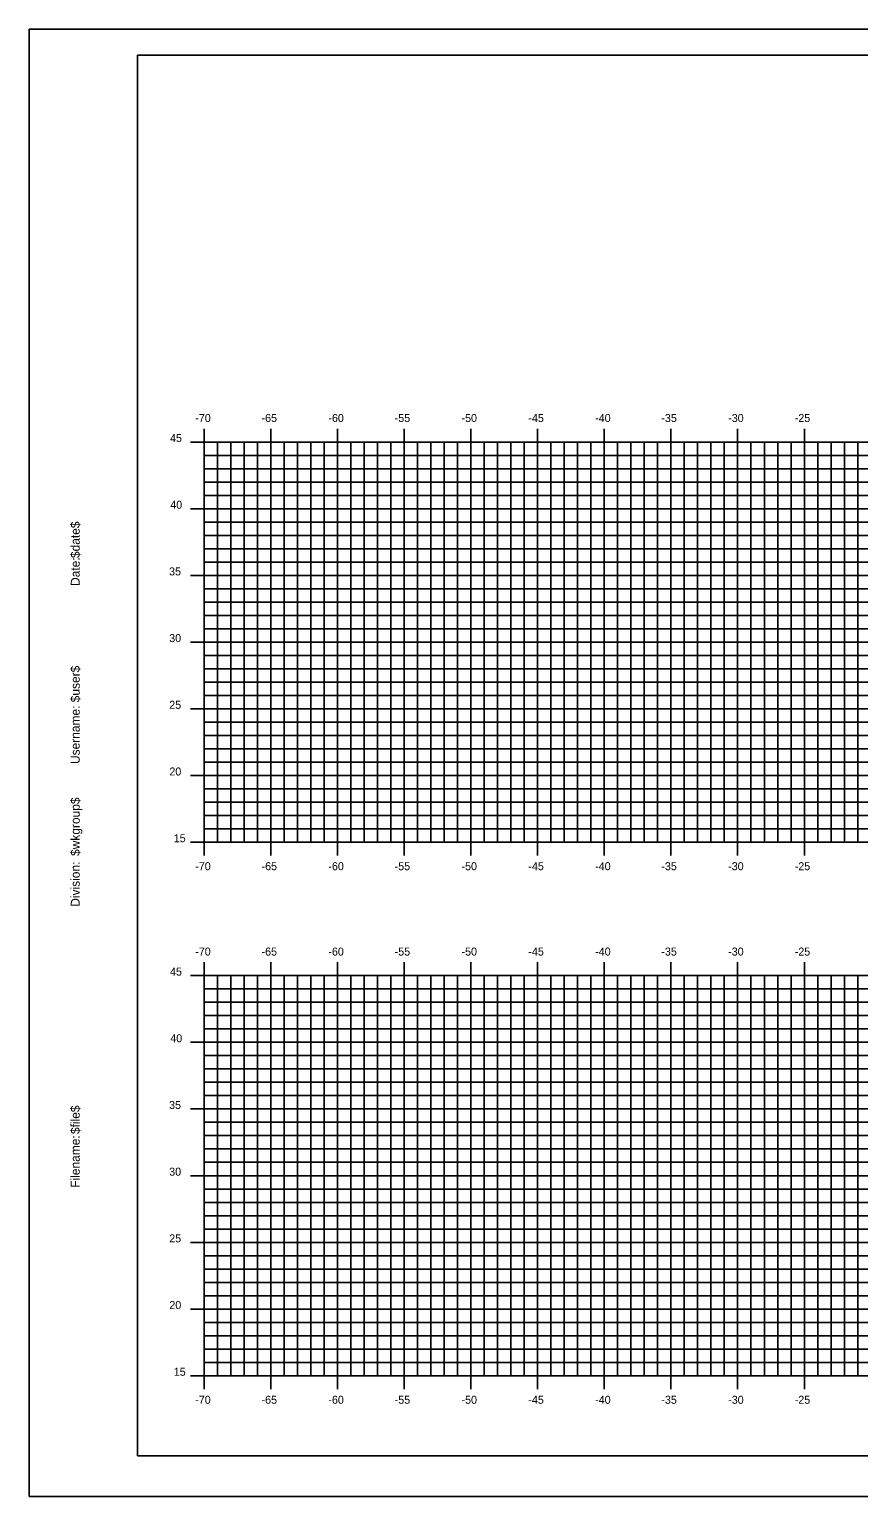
# Model space of a CAD drawing. Extents: x 1037709 to 1037879, y 394883 to 394993.
# Drawn here: x 1037709.1 to 1037771.2, y 394882.6 to 394992.6 of the extents above; entities that cross this region are included whole.
import ezdxf

# ---------------------------------------------------------------- set-up
doc = ezdxf.new("R2010")
doc.units = 0
for name, color, linetype in [('BORDER', 7, 'Continuous'), ('H_V ANNOTATION', 7, 'Continuous'), ('MAJOR', 7, 'Continuous'), ('MINOR', 7, 'Continuous'), ('PLOT BOUNDARY', 7, 'Continuous')]:
    doc.layers.add(name, color=color, linetype=linetype)

msp = doc.modelspace()

# ---------------------------------------------------------------- linework, layer by layer
at = {"layer": 'BORDER'}
for p, q in [((1037877.16, 394990.69), (1037717.16, 394990.69)), ((1037717.16, 394990.69), (1037717.16, 394885.69)), ((1037717.16, 394885.69), (1037877.16, 394885.69))]:
    msp.add_line(p, q, dxfattribs=at)
at = {"layer": 'MAJOR'}
for p, q in [((1037721.15, 394961.69), (1037722.16, 394961.69)), ((1037722.16, 394962.69), (1037722.16, 394961.69)), ((1037722.16, 394961.69), (1037862.16, 394961.69)), ((1037722.16, 394931.69), (1037722.16, 394961.69)), ((1037727.16, 394962.69), (1037727.16, 394961.69)), ((1037727.16, 394931.69), (1037727.16, 394961.69)), ((1037732.16, 394962.69), (1037732.16, 394961.69)), ((1037732.16, 394931.69), (1037732.16, 394961.69)), ((1037737.16, 394962.69), (1037737.16, 394961.69)), ((1037737.16, 394931.69), (1037737.16, 394961.69)), ((1037742.16, 394962.69), (1037742.16, 394961.69)), ((1037742.16, 394931.69), (1037742.16, 394961.69)), ((1037747.16, 394962.69), (1037747.16, 394961.69)), ((1037747.16, 394931.69), (1037747.16, 394961.69)), ((1037752.16, 394962.69), (1037752.16, 394961.69)), ((1037752.16, 394931.69), (1037752.16, 394961.69)), ((1037757.16, 394962.69), (1037757.16, 394961.69)), ((1037757.16, 394931.69), (1037757.16, 394961.69)), ((1037762.16, 394962.69), (1037762.16, 394961.69)), ((1037762.16, 394931.69), (1037762.16, 394961.69)), ((1037767.16, 394962.69), (1037767.16, 394961.69)), ((1037767.16, 394931.69), (1037767.16, 394961.69)), ((1037721.15, 394956.69), (1037722.16, 394956.69)), ((1037722.16, 394956.69), (1037862.16, 394956.69)), ((1037721.15, 394951.69), (1037722.16, 394951.69)), ((1037722.16, 394951.69), (1037862.16, 394951.69)), ((1037721.15, 394946.69), (1037722.16, 394946.69)), ((1037722.16, 394946.69), (1037862.16, 394946.69)), ((1037721.15, 394941.69), (1037722.16, 394941.69)), ((1037722.16, 394941.69), (1037862.16, 394941.69)), ((1037721.15, 394936.69), (1037722.16, 394936.69)), ((1037722.16, 394936.69), (1037862.16, 394936.69)), ((1037721.15, 394931.69), (1037722.16, 394931.69)), ((1037722.16, 394931.69), (1037862.16, 394931.69)), ((1037722.16, 394930.68), (1037722.16, 394931.69)), ((1037727.16, 394930.68), (1037727.16, 394931.69)), ((1037732.16, 394930.68), (1037732.16, 394931.69)), ((1037737.16, 394930.68), (1037737.16, 394931.69)), ((1037742.16, 394930.68), (1037742.16, 394931.69)), ((1037747.16, 394930.68), (1037747.16, 394931.69)), ((1037752.16, 394930.68), (1037752.16, 394931.69)), ((1037757.16, 394930.68), (1037757.16, 394931.69)), ((1037762.16, 394930.68), (1037762.16, 394931.69)), ((1037767.16, 394930.68), (1037767.16, 394931.69)), ((1037722.16, 394922.69), (1037722.16, 394921.69)), ((1037727.16, 394922.69), (1037727.16, 394921.69)), ((1037732.16, 394922.69), (1037732.16, 394921.69)), ((1037737.16, 394922.69), (1037737.16, 394921.69)), ((1037742.16, 394922.69), (1037742.16, 394921.69)), ((1037747.16, 394922.69), (1037747.16, 394921.69)), ((1037752.16, 394922.69), (1037752.16, 394921.69)), ((1037757.16, 394922.69), (1037757.16, 394921.69)), ((1037762.16, 394922.69), (1037762.16, 394921.69)), ((1037767.16, 394922.69), (1037767.16, 394921.69)), ((1037721.15, 394921.69), (1037722.16, 394921.69)), ((1037722.16, 394921.69), (1037862.16, 394921.69)), ((1037722.16, 394891.69), (1037722.16, 394921.69)), ((1037727.16, 394891.69), (1037727.16, 394921.69)), ((1037732.16, 394891.69), (1037732.16, 394921.69)), ((1037737.16, 394891.69), (1037737.16, 394921.69)), ((1037742.16, 394891.69), (1037742.16, 394921.69)), ((1037747.16, 394891.69), (1037747.16, 394921.69)), ((1037752.16, 394891.69), (1037752.16, 394921.69)), ((1037757.16, 394891.69), (1037757.16, 394921.69)), ((1037762.16, 394891.69), (1037762.16, 394921.69)), ((1037767.16, 394891.69), (1037767.16, 394921.69)), ((1037721.15, 394916.69), (1037722.16, 394916.69)), ((1037722.16, 394916.69), (1037862.16, 394916.69)), ((1037721.15, 394911.69), (1037722.16, 394911.69)), ((1037722.16, 394911.69), (1037862.16, 394911.69)), ((1037721.15, 394906.69), (1037722.16, 394906.69)), ((1037722.16, 394906.69), (1037862.16, 394906.69)), ((1037721.15, 394901.69), (1037722.16, 394901.69)), ((1037722.16, 394901.69), (1037862.16, 394901.69)), ((1037721.15, 394896.69), (1037722.16, 394896.69)), ((1037722.16, 394896.69), (1037862.16, 394896.69)), ((1037721.15, 394891.69), (1037722.16, 394891.69)), ((1037722.16, 394891.69), (1037862.16, 394891.69)), ((1037722.16, 394890.68), (1037722.16, 394891.69)), ((1037727.16, 394890.68), (1037727.16, 394891.69)), ((1037732.16, 394890.68), (1037732.16, 394891.69)), ((1037737.16, 394890.68), (1037737.16, 394891.69)), ((1037742.16, 394890.68), (1037742.16, 394891.69)), ((1037747.16, 394890.68), (1037747.16, 394891.69)), ((1037752.16, 394890.68), (1037752.16, 394891.69)), ((1037757.16, 394890.68), (1037757.16, 394891.69)), ((1037762.16, 394890.68), (1037762.16, 394891.69)), ((1037767.16, 394890.68), (1037767.16, 394891.69))]:
    msp.add_line(p, q, dxfattribs=at)
at = {"layer": 'MINOR'}
for p, q in [((1037723.16, 394931.69), (1037723.16, 394961.69)), ((1037724.16, 394931.69), (1037724.16, 394961.69)), ((1037725.16, 394931.69), (1037725.16, 394961.69)), ((1037726.16, 394931.69), (1037726.16, 394961.69)), ((1037728.16, 394931.69), (1037728.16, 394961.69)), ((1037729.16, 394931.69), (1037729.16, 394961.69)), ((1037730.16, 394931.69), (1037730.16, 394961.69)), ((1037731.16, 394931.69), (1037731.16, 394961.69)), ((1037733.16, 394931.69), (1037733.16, 394961.69)), ((1037734.16, 394931.69), (1037734.16, 394961.69)), ((1037735.16, 394931.69), (1037735.16, 394961.69)), ((1037736.16, 394931.69), (1037736.16, 394961.69)), ((1037738.16, 394931.69), (1037738.16, 394961.69)), ((1037739.16, 394931.69), (1037739.16, 394961.69)), ((1037740.16, 394931.69), (1037740.16, 394961.69)), ((1037741.16, 394931.69), (1037741.16, 394961.69)), ((1037743.16, 394931.69), (1037743.16, 394961.69)), ((1037744.16, 394931.69), (1037744.16, 394961.69)), ((1037745.16, 394931.69), (1037745.16, 394961.69)), ((1037746.16, 394931.69), (1037746.16, 394961.69)), ((1037748.16, 394931.69), (1037748.16, 394961.69)), ((1037749.16, 394931.69), (1037749.16, 394961.69)), ((1037750.16, 394931.69), (1037750.16, 394961.69)), ((1037751.16, 394931.69), (1037751.16, 394961.69)), ((1037753.16, 394931.69), (1037753.16, 394961.69)), ((1037754.16, 394931.69), (1037754.16, 394961.69)), ((1037755.16, 394931.69), (1037755.16, 394961.69)), ((1037756.16, 394931.69), (1037756.16, 394961.69)), ((1037758.16, 394931.69), (1037758.16, 394961.69)), ((1037759.16, 394931.69), (1037759.16, 394961.69)), ((1037760.16, 394931.69), (1037760.16, 394961.69)), ((1037761.16, 394931.69), (1037761.16, 394961.69)), ((1037763.16, 394931.69), (1037763.16, 394961.69)), ((1037764.16, 394931.69), (1037764.16, 394961.69)), ((1037765.16, 394931.69), (1037765.16, 394961.69)), ((1037766.16, 394931.69), (1037766.16, 394961.69)), ((1037768.16, 394931.69), (1037768.16, 394961.69)), ((1037769.16, 394931.69), (1037769.16, 394961.69)), ((1037770.16, 394931.69), (1037770.16, 394961.69)), ((1037771.16, 394931.69), (1037771.16, 394961.69)), ((1037722.16, 394960.69), (1037862.16, 394960.69)), ((1037722.16, 394960.69), (1037723.16, 394960.69)), ((1037722.16, 394959.69), (1037862.16, 394959.69)), ((1037722.16, 394959.69), (1037723.16, 394959.69)), ((1037722.16, 394958.69), (1037862.16, 394958.69)), ((1037722.16, 394958.69), (1037723.16, 394958.69)), ((1037722.16, 394957.69), (1037862.16, 394957.69)), ((1037722.16, 394957.69), (1037723.16, 394957.69)), ((1037722.16, 394955.69), (1037862.16, 394955.69)), ((1037722.16, 394955.69), (1037723.16, 394955.69)), ((1037722.16, 394954.69), (1037862.16, 394954.69)), ((1037722.16, 394954.69), (1037723.16, 394954.69)), ((1037722.16, 394953.69), (1037862.16, 394953.69)), ((1037722.16, 394953.69), (1037723.16, 394953.69)), ((1037722.16, 394952.69), (1037862.16, 394952.69)), ((1037722.16, 394952.69), (1037723.16, 394952.69)), ((1037722.16, 394950.69), (1037862.16, 394950.69)), ((1037722.16, 394950.69), (1037723.16, 394950.69)), ((1037722.16, 394949.69), (1037862.16, 394949.69)), ((1037722.16, 394949.69), (1037723.16, 394949.69)), ((1037722.16, 394948.69), (1037862.16, 394948.69)), ((1037722.16, 394948.69), (1037723.16, 394948.69)), ((1037722.16, 394947.69), (1037862.16, 394947.69)), ((1037722.16, 394947.69), (1037723.16, 394947.69)), ((1037722.16, 394945.69), (1037862.16, 394945.69)), ((1037722.16, 394945.69), (1037723.16, 394945.69)), ((1037722.16, 394944.69), (1037862.16, 394944.69)), ((1037722.16, 394944.69), (1037723.16, 394944.69)), ((1037722.16, 394943.69), (1037862.16, 394943.69)), ((1037722.16, 394943.69), (1037723.16, 394943.69)), ((1037722.16, 394942.69), (1037862.16, 394942.69)), ((1037722.16, 394942.69), (1037723.16, 394942.69)), ((1037722.16, 394940.69), (1037862.16, 394940.69)), ((1037722.16, 394940.69), (1037723.16, 394940.69)), ((1037722.16, 394939.69), (1037862.16, 394939.69)), ((1037722.16, 394939.69), (1037723.16, 394939.69)), ((1037722.16, 394938.69), (1037862.16, 394938.69)), ((1037722.16, 394938.69), (1037723.16, 394938.69)), ((1037722.16, 394937.69), (1037862.16, 394937.69)), ((1037722.16, 394937.69), (1037723.16, 394937.69)), ((1037722.16, 394935.69), (1037862.16, 394935.69)), ((1037722.16, 394935.69), (1037723.16, 394935.69)), ((1037722.16, 394934.69), (1037862.16, 394934.69)), ((1037722.16, 394934.69), (1037723.16, 394934.69)), ((1037722.16, 394933.69), (1037862.16, 394933.69)), ((1037722.16, 394933.69), (1037723.16, 394933.69)), ((1037722.16, 394932.69), (1037862.16, 394932.69)), ((1037722.16, 394932.69), (1037723.16, 394932.69)), ((1037723.16, 394891.69), (1037723.16, 394921.69)), ((1037724.16, 394891.69), (1037724.16, 394921.69)), ((1037725.16, 394891.69), (1037725.16, 394921.69)), ((1037726.16, 394891.69), (1037726.16, 394921.69)), ((1037728.16, 394891.69), (1037728.16, 394921.69)), ((1037729.16, 394891.69), (1037729.16, 394921.69)), ((1037730.16, 394891.69), (1037730.16, 394921.69)), ((1037731.16, 394891.69), (1037731.16, 394921.69)), ((1037733.16, 394891.69), (1037733.16, 394921.69)), ((1037734.16, 394891.69), (1037734.16, 394921.69)), ((1037735.16, 394891.69), (1037735.16, 394921.69)), ((1037736.16, 394891.69), (1037736.16, 394921.69)), ((1037738.16, 394891.69), (1037738.16, 394921.69)), ((1037739.16, 394891.69), (1037739.16, 394921.69)), ((1037740.16, 394891.69), (1037740.16, 394921.69)), ((1037741.16, 394891.69), (1037741.16, 394921.69)), ((1037743.16, 394891.69), (1037743.16, 394921.69)), ((1037744.16, 394891.69), (1037744.16, 394921.69)), ((1037745.16, 394891.69), (1037745.16, 394921.69)), ((1037746.16, 394891.69), (1037746.16, 394921.69)), ((1037748.16, 394891.69), (1037748.16, 394921.69)), ((1037749.16, 394891.69), (1037749.16, 394921.69)), ((1037750.16, 394891.69), (1037750.16, 394921.69)), ((1037751.16, 394891.69), (1037751.16, 394921.69)), ((1037753.16, 394891.69), (1037753.16, 394921.69)), ((1037754.16, 394891.69), (1037754.16, 394921.69)), ((1037755.16, 394891.69), (1037755.16, 394921.69)), ((1037756.16, 394891.69), (1037756.16, 394921.69)), ((1037758.16, 394891.69), (1037758.16, 394921.69)), ((1037759.16, 394891.69), (1037759.16, 394921.69)), ((1037760.16, 394891.69), (1037760.16, 394921.69)), ((1037761.16, 394891.69), (1037761.16, 394921.69)), ((1037763.16, 394891.69), (1037763.16, 394921.69)), ((1037764.16, 394891.69), (1037764.16, 394921.69)), ((1037765.16, 394891.69), (1037765.16, 394921.69)), ((1037766.16, 394891.69), (1037766.16, 394921.69)), ((1037768.16, 394891.69), (1037768.16, 394921.69)), ((1037769.16, 394891.69), (1037769.16, 394921.69)), ((1037770.16, 394891.69), (1037770.16, 394921.69)), ((1037771.16, 394891.69), (1037771.16, 394921.69)), ((1037722.16, 394920.69), (1037862.16, 394920.69)), ((1037722.16, 394920.69), (1037723.16, 394920.69)), ((1037722.16, 394919.69), (1037862.16, 394919.69)), ((1037722.16, 394919.69), (1037723.16, 394919.69)), ((1037722.16, 394918.69), (1037862.16, 394918.69)), ((1037722.16, 394918.69), (1037723.16, 394918.69)), ((1037722.16, 394917.69), (1037862.16, 394917.69)), ((1037722.16, 394917.69), (1037723.16, 394917.69)), ((1037722.16, 394915.69), (1037862.16, 394915.69)), ((1037722.16, 394915.69), (1037723.16, 394915.69)), ((1037722.16, 394914.69), (1037862.16, 394914.69)), ((1037722.16, 394914.69), (1037723.16, 394914.69)), ((1037722.16, 394913.69), (1037862.16, 394913.69)), ((1037722.16, 394913.69), (1037723.16, 394913.69)), ((1037722.16, 394912.69), (1037862.16, 394912.69)), ((1037722.16, 394912.69), (1037723.16, 394912.69)), ((1037722.16, 394910.69), (1037862.16, 394910.69)), ((1037722.16, 394910.69), (1037723.16, 394910.69)), ((1037722.16, 394909.69), (1037862.16, 394909.69)), ((1037722.16, 394909.69), (1037723.16, 394909.69)), ((1037722.16, 394908.69), (1037862.16, 394908.69)), ((1037722.16, 394908.69), (1037723.16, 394908.69)), ((1037722.16, 394907.69), (1037862.16, 394907.69)), ((1037722.16, 394907.69), (1037723.16, 394907.69)), ((1037722.16, 394905.69), (1037862.16, 394905.69)), ((1037722.16, 394905.69), (1037723.16, 394905.69)), ((1037722.16, 394904.69), (1037862.16, 394904.69)), ((1037722.16, 394904.69), (1037723.16, 394904.69)), ((1037722.16, 394903.69), (1037862.16, 394903.69)), ((1037722.16, 394903.69), (1037723.16, 394903.69)), ((1037722.16, 394902.69), (1037862.16, 394902.69)), ((1037722.16, 394902.69), (1037723.16, 394902.69)), ((1037722.16, 394900.69), (1037862.16, 394900.69)), ((1037722.16, 394900.69), (1037723.16, 394900.69)), ((1037722.16, 394899.69), (1037862.16, 394899.69)), ((1037722.16, 394899.69), (1037723.16, 394899.69)), ((1037722.16, 394898.69), (1037862.16, 394898.69)), ((1037722.16, 394898.69), (1037723.16, 394898.69)), ((1037722.16, 394897.69), (1037862.16, 394897.69)), ((1037722.16, 394897.69), (1037723.16, 394897.69)), ((1037722.16, 394895.69), (1037862.16, 394895.69)), ((1037722.16, 394895.69), (1037723.16, 394895.69)), ((1037722.16, 394894.69), (1037862.16, 394894.69)), ((1037722.16, 394894.69), (1037723.16, 394894.69)), ((1037722.16, 394893.69), (1037862.16, 394893.69)), ((1037722.16, 394893.69), (1037723.16, 394893.69)), ((1037722.16, 394892.69), (1037862.16, 394892.69)), ((1037722.16, 394892.69), (1037723.16, 394892.69))]:
    msp.add_line(p, q, dxfattribs=at)
at = {"layer": 'PLOT BOUNDARY'}
msp.add_lwpolyline([(1037709.06, 394882.63), (1037879.06, 394882.63), (1037879.06, 394992.63), (1037709.06, 394992.63)], close=True, dxfattribs=at)

# ---------------------------------------------------------------- texts
at = {"layer": 'BORDER'}
for s, p in [('$date$', (1037712.84, 394952.99)), ('Date:', (1037712.84, 394950.9)), ('$user$', (1037712.84, 394942.18)), ('Username:', (1037712.84, 394937.55)), ('$wkgroup$', (1037712.84, 394930.66)), ('Division:', (1037712.84, 394926.85)), ('$file$', (1037712.84, 394909.81)), ('Filename:', (1037712.84, 394905.78))]:
    msp.add_text(s, height=0.67, rotation=90, dxfattribs=at).set_placement(p)
at = {"layer": 'H_V ANNOTATION'}
for s, p in [('-70', (1037721.5, 394963.19)), ('-65', (1037726.47, 394963.19)), ('-60', (1037731.48, 394963.19)), ('-55', (1037736.45, 394963.19)), ('-50', (1037741.46, 394963.19)), ('-45', (1037746.47, 394963.19)), ('-40', (1037751.48, 394963.19)), ('-35', (1037756.44, 394963.19)), ('-30', (1037761.45, 394963.19)), ('-25', (1037766.44, 394963.19)), ('45', (1037719.61, 394961.69)), ('40', (1037719.63, 394956.69)), ('35', (1037719.54, 394951.69)), ('30', (1037719.55, 394946.69)), ('25', (1037719.55, 394941.69)), ('20', (1037719.56, 394936.69)), ('15', (1037719.89, 394931.69)), ('-70', (1037721.5, 394929.59)), ('-65', (1037726.47, 394929.59)), ('-60', (1037731.48, 394929.59)), ('-55', (1037736.45, 394929.59)), ('-50', (1037741.46, 394929.59)), ('-45', (1037746.47, 394929.59)), ('-40', (1037751.48, 394929.59)), ('-35', (1037756.44, 394929.59)), ('-30', (1037761.45, 394929.59)), ('-25', (1037766.44, 394929.59)), ('-70', (1037721.5, 394923.19)), ('-65', (1037726.47, 394923.19)), ('-60', (1037731.48, 394923.19)), ('-55', (1037736.45, 394923.19)), ('-50', (1037741.46, 394923.19)), ('-45', (1037746.47, 394923.19)), ('-40', (1037751.48, 394923.19)), ('-35', (1037756.44, 394923.19)), ('-30', (1037761.45, 394923.19)), ('-25', (1037766.44, 394923.19)), ('45', (1037719.61, 394921.69)), ('40', (1037719.63, 394916.69)), ('35', (1037719.54, 394911.69)), ('30', (1037719.55, 394906.69)), ('25', (1037719.55, 394901.69)), ('20', (1037719.56, 394896.69)), ('15', (1037719.89, 394891.69)), ('-70', (1037721.5, 394889.59)), ('-65', (1037726.47, 394889.59)), ('-60', (1037731.48, 394889.59)), ('-55', (1037736.45, 394889.59)), ('-50', (1037741.46, 394889.59)), ('-45', (1037746.47, 394889.59)), ('-40', (1037751.48, 394889.59)), ('-35', (1037756.44, 394889.59)), ('-30', (1037761.45, 394889.59)), ('-25', (1037766.44, 394889.59))]:
    msp.add_text(s, height=0.6, dxfattribs=at).set_placement(p)
at = {"layer": 'MAJOR'}
for p in [(1037722.15, 394931.69), (1037722.15, 394891.69)]:
    msp.add_text('-', height=0.006, dxfattribs=at).set_placement(p)

doc.saveas('drawing.dxf')
